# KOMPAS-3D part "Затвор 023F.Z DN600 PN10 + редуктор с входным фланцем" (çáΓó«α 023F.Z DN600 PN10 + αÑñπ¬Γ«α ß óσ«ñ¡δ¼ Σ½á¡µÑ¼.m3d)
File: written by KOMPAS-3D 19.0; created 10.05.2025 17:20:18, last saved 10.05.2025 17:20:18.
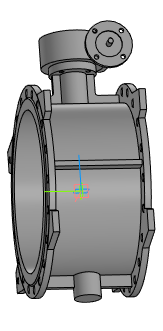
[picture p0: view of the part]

Document properties: Полное имя файла: Затвор 023F.Z DN600 PN10 + редуктор с входным фланцем.a3d

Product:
- Part/product: Затвор 023F.Z DN600 PN10 + редуктор с входным фланцем
    Масса: 389.287

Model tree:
1. Операция без истории:1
